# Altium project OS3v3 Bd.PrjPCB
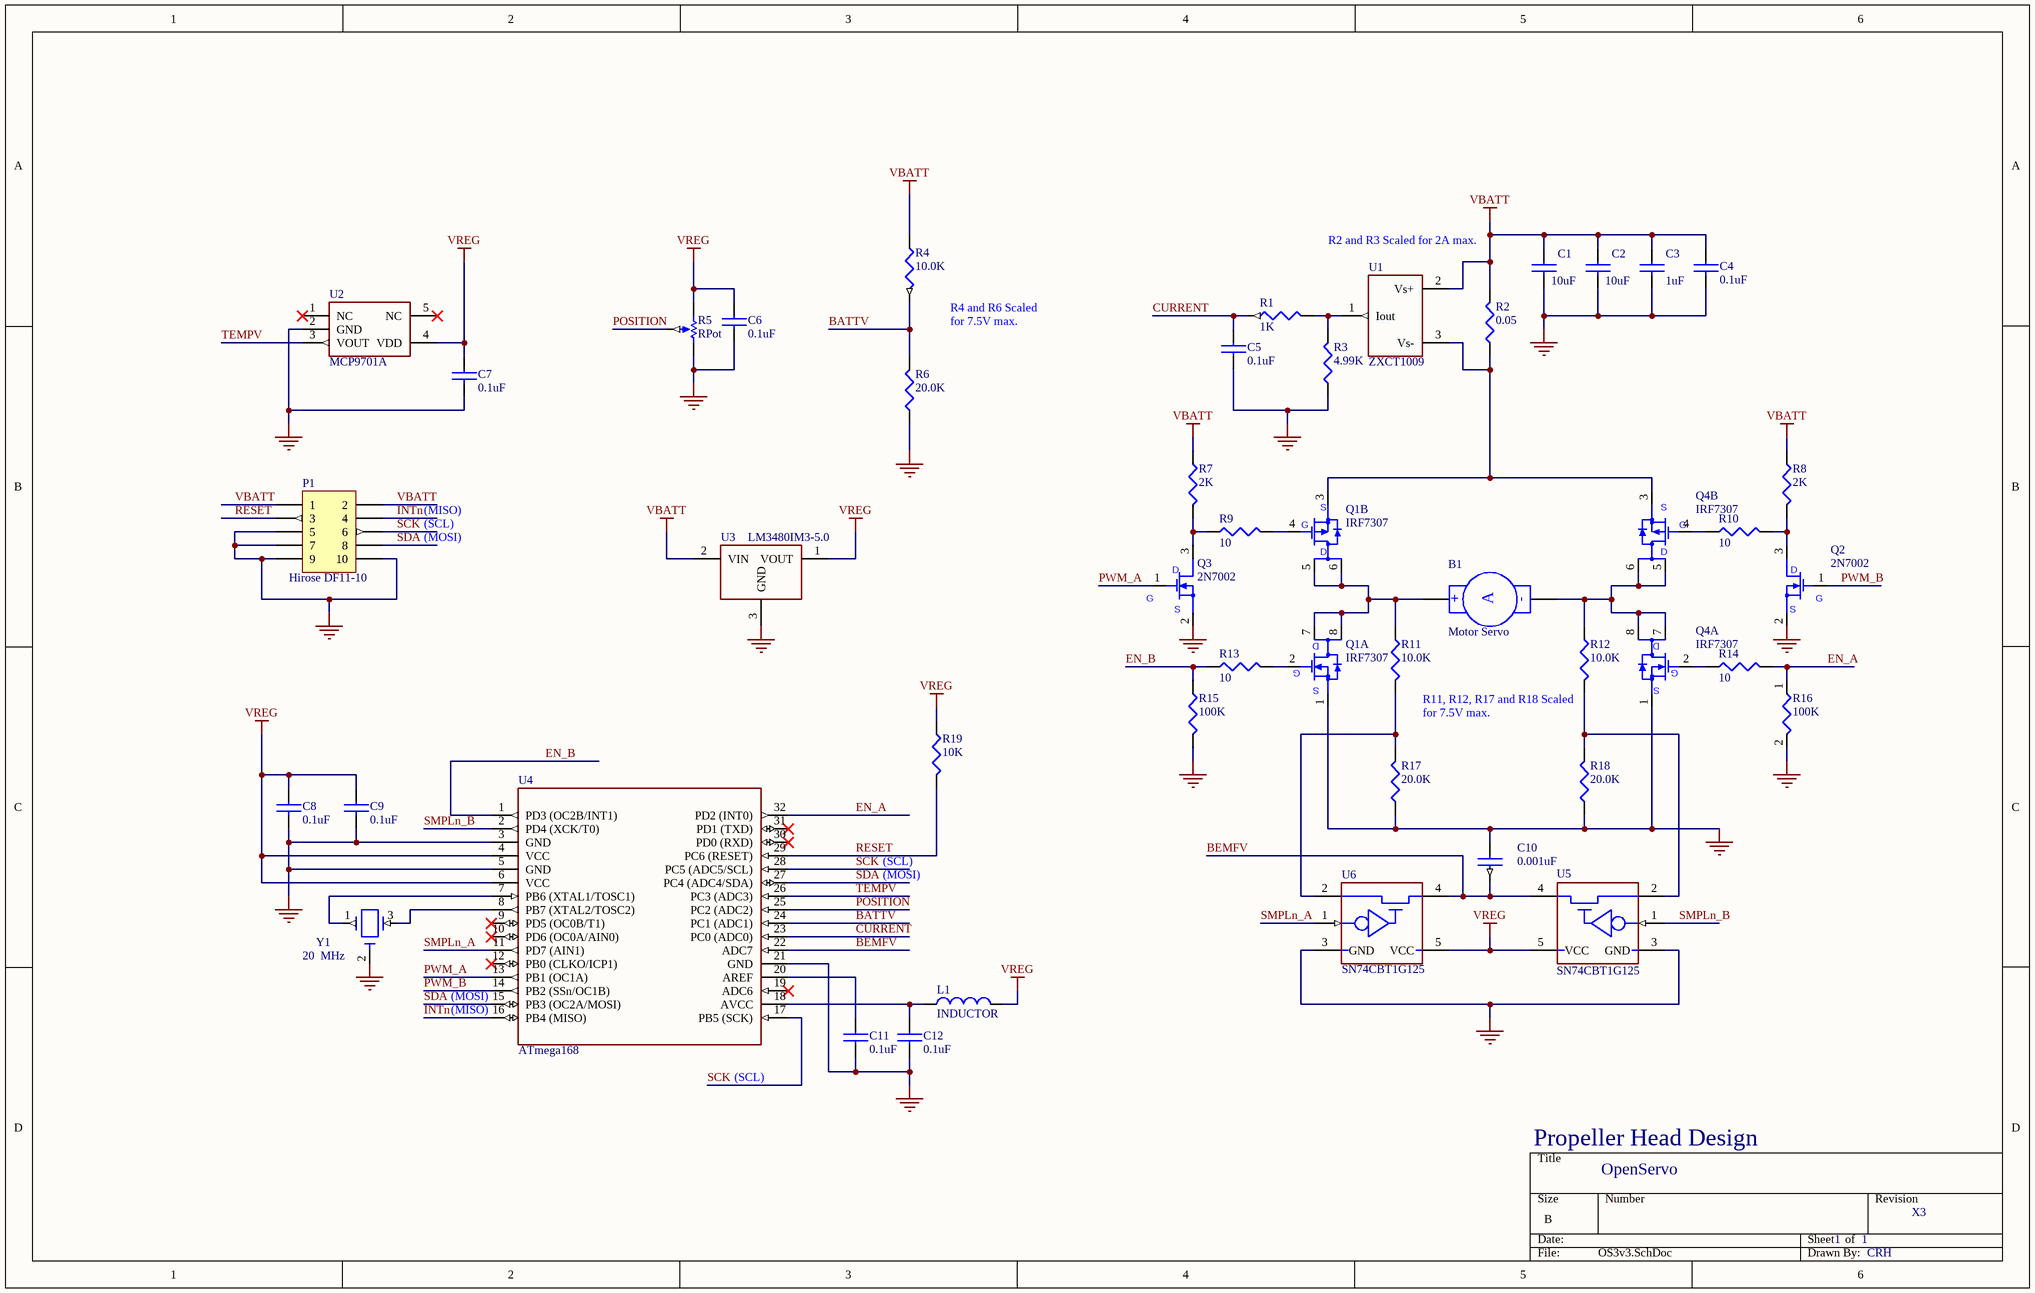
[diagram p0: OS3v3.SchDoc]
1 sheet, 45 parts. Net scope: global (net labels, ports and power ports of the same name join across sheets).
Board files: OSXv3_Pallet.PcbDoc, OS3v3.PcbDoc

## Sheet OS3v3.SchDoc: OpenServo
size B; CompanyName: Propeller Head Design; DrawnBy: CRH; Revision: X3; SheetNumber: 1; SheetTotal: 1

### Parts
B1  Motor Servo  [Servo Pads]  (no BOM)
C1  10uF  [C1206]
C2  10uF  [C1206]
C3  1uF  [C0603]
C4  0.1uF  [C0603]
C5  0.1uF  [C0603]
C6  0.1uF  [C0603]
C7  0.1uF  [C0603]
C8  0.1uF  [C0603]
C9  0.1uF  [C0603]
C10  0.001uF  [C0603]
C11  0.1uF  [C0603]
C12  0.1uF  [C0603]
L1  INDUCTOR  [C0603]
P1  Hirose DF11-10  [FD11-10E]
Q1  IRF7307  [SO8]  (parts A,B of 2)
Q2  2N7002  [SOT23-3]
Q3  2N7002  [SOT23-3]
Q4  IRF7307  [SO8]  (parts A,B of 2)
R1  1K  [R0603]
R2  0.05  [R0805]
R3  4.99K  [R0603]
R4  10.0K  [R0603]
R5  RPot  (no BOM)
R6  20.0K  [R0603]
R7  2K  [R0603]
R8  2K  [R0603]
R9  10  [R0603]
R10  10  [R0603]
R11  10.0K  [R0603]
R12  10.0K  [R0603]
R13  10  [R0603]
R14  10  [R0603]
R15  100K  [R0603]
R16  100K  [R0603]
R17  20.0K  [R0603]
R18  20.0K  [R0603]
R19  10K  [R0603]
U1  ZXCT1009  [SOT23-3F]
U2  MCP9701A  [SC70 -5]
U3  LM3480IM3-5.0  [SOT23-3]
U4  ATmega168  [32M1-A_N]
U5  SN74CBT1G125  [SC70 -5]
U6  SN74CBT1G125  [SC70 -5]
Y1  20  MHz  [MXC7T]

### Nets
GND: C1.2 C2.2 C3.2 C4.2 C5.2 C6.2 C7.2 C8.2 C9.2 C10.1 C11.2 C12.2 P1.5 P1.7 P1.9 P1.10 Q1.1(S) Q2.2(S) Q3.2(S) Q4.1(S) R3.2 R5.2(BOT) R6.2 R15.2 R16.2 R17.2 R18.2 U2.2(GND) U3.3(GND) U4.3(GND) U4.5(GND) U4.21(GND) U5.3(GND) U6.3(GND) Y1.2
VBATT: C1.1 C2.1 C3.1 C4.1 P1.1 P1.2 R2.1 R4.1 R7.1 R8.1 U1.2(Vs+) U3.2(VIN)
VREG: C6.1 C7.1 C8.1 C9.1 L1.2 R5.1(TOP) R19.1 U2.4(VDD) U3.1(VOUT) U4.4(VCC) U4.6(VCC) U5.5(VCC) U6.5(VCC)
BATTV: R4.2 R6.1 U4.24(PC1_(ADC1))
BEMFV: C10.2 U4.22(ADC7) U5.4(B) U6.4(B)
CURRENT: C5.1 R1.1 U4.23(PC0_(ADC0))
EN_A: R14.1 R16.1 U4.32(PD2_(INT0))
EN_B: R13.2 R15.1 U4.1(PD3_(OC2B/INT1))
INTn: P1.4 U4.16(PB4_(MISO))
POSITION: R5.3(TAP) U4.25(PC2_(ADC2))
PWM_A: Q3.1(G) U4.13(PB1_(OC1A))
PWM_B: Q2.1(G) U4.14(PB2_(SSn/OC1B))
RESET: P1.3 R19.2 U4.29(PC6_(RESET))
SCK: P1.6 U4.17(PB5_(SCK)) U4.28(PC5_(ADC5/SCL))
SDA: P1.8 U4.15(PB3_(OC2A/MOSI)) U4.27(PC4_(ADC4/SDA))
SMPLn_A: U4.11(PD7_(AIN1)) U6.1(OEn)
SMPLn_B: U4.2(PD4_(XCK/T0)) U5.1(OEn)
TEMPV: U2.3(VOUT) U4.26(PC3_(ADC3))
NetB1_1: B1.1(+) Q1.5(D) Q1.6(D) Q1.7(D) Q1.8(D) R11.1
NetB1_2: B1.2(-) Q4.5(D) Q4.6(D) Q4.7(D) Q4.8(D) R12.1
NetC11_1: C11.1 U4.20(AREF)
NetC12_1: C12.1 L1.1 U4.18(AVCC)
NetQ1_2: Q1.2(G) R13.1
NetQ1_3: Q1.3(S) Q4.3(S) R2.2 U1.3(Vs-)
NetQ1_4: Q1.4(G) R9.1
NetQ2_3: Q2.3(D) R8.2 R10.2
NetQ3_3: Q3.3(D) R7.2 R9.2
NetQ4_2: Q4.2(G) R14.2
NetQ4_4: Q4.4(G) R10.1
NetR1_2: R1.2 R3.1 U1.1(Iout)
NetR11_2: R11.2 R17.1 U6.2(A)
NetR12_2: R12.2 R18.1 U5.2(A)
NetU4_7: U4.7(PB6_(XTAL1/TOSC1)) Y1.1
NetU4_8: U4.8(PB7_(XTAL2/TOSC2)) Y1.3

Not connected (* = marked no-connect by the designer): U2 1(NC)* 5(NC)*; U4 9(PD5_(OC0B/T1))* 10(PD6_(OC0A/AIN0))* 12(PB0_(CLKO/ICP1))* 19(ADC6)* 30(PD0_(RXD))* 31(PD1_(TXD))*

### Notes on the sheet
- R2 and R3 Scaled for 2A max.
- R4 and R6 Scaled
- for 7.5V max.
- (MOSI)
- (SCL)
- (MISO)
- (near R12) R11, R12, R17 and R18 Scaled
- (near U4) (MOSI)
- (near U4) (MISO)

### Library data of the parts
B1 = Motor Servo: Servo Motor
C1 C2 = CAP NP: Manufacturer: Panasonic; Vendor: DigiKey; Vendor P/N: PCC2326CT-ND; Item Description: Capacitor, 10uF, X5R, ±20%, 25V, Ceramic, SM, 1206; Mfg. P/N: ECJ-3YB1E106M
C3 = CAP NP: Manufacturer: Panasonic; Vendor: DigiKey; Vendor P/N: PCC2224CT-ND; Item Description: Capacitor, 1uF, X5R, ±10%, 16V, Ceramic, SM, 0603; Mfg. P/N: ECJ-1VB1C105K
C4-C9 C11 C12 = CAP NP: Manufacturer: Panasonic; Vendor: DigiKey; Vendor P/N: PCC1762CT-ND; Item Description: Capacitor, 0.1uF, X7R, ±10%, 16V, Ceramic, SM, 0603; Mfg. P/N: ECJ-1VB1C104K
C10 = CAP NP: Manufacturer: Panasonic; Vendor: DigiKey; Vendor P/N: PCC1772CT-ND; Item Description: Capacitor, 0.001uF, X7R, ±10%, 50V, Ceramic, SM, 0603; Mfg. P/N: ECJ-1VB1H102K
L1 = INDUCTOR: Manufacturer: TDK; Item Description: Inductor, 10uH, 3mA, 10%; Mfg. P/N: MLF1608E100K; Vendor: DigiKey; Vendor P/N: 445-1025-1-ND
P1 = Header 5X2: Header, 5-Pin, Dual row; Item Description: Connector, TH, 2mm, 2x10; Mfg. P/N: DF11-10DP-2DSA(24); Vendor: DigiKey; Vendor P/N: H10232-ND
Q1 Q4 = IRF7307: Manufacturer: IRF; Item Description: MOSFET, Dual, N/P, 20/-20V, 4.3/-3.4A; Mfg. P/N: IRF7307TRPBF; Vendor: DigiKey; Vendor P/N: IRF7307PBFCT-ND
Q2 Q3 = 2N7002: N FET; Manufacturer: Diodes Inc.; Vendor: DigiKey; Vendor P/N: 2N7002-FDICT-ND; Item Description: FET, N, 60V, 115mA, Vgs 2.5V, SOT23
R1 = R: Manufacturer: Panasonic; Vendor: DigiKey; Vendor P/N: P1.0KGCT-ND; Item Description: Resistor, CF, 1K Ohms, 5%, 0.1W, SM, 0603; Mfg. P/N: ERJ-3GEYJ102V
R2 = R: 1%; Manufacturer: Susumu; Vendor: DigiKey; Vendor P/N: RL12T.05GCT-ND; Item Description: Resistor, CF, 0.05 Ohm, 0.25W,  2%, SM, 0805; Mfg. P/N: RL1220T-R050-G
R3 = R: 1%; Manufacturer: Panasonic; Vendor: DigiKey; Vendor P/N: P4.99KHCT-ND; Item Description: Resistor, CF, 4.99K Ohm, 0.06W, 1%, SM, 0603; Mfg. P/N: ERJ-3EKF4991V
R4 R11 R12 = R: 1%; Manufacturer: Panasonic; Vendor: DigiKey; Vendor P/N: P10.0KHCT-ND; Item Description: Resistor, CF, 10.0K Ohm, 1%, 0.06W, SM, 0603; Mfg. P/N: ERJ-3EKF1002V
R5 = RPot: Potentiometer; Item Description: Servo Pot
R6 R17 R18 = R: 1%; Manufacturer: Panasonic; Vendor: DigiKey; Vendor P/N: P20.0KHCT-ND; Item Description: Resistor, CF, 20.0K Ohm, 0.06W, 1%, SM, 0603; Mfg. P/N: ERJ-3EKF2002V
R7 R8 = R: Manufacturer: Panasonic; Vendor: DigiKey; Vendor P/N: P2.0KGCT-ND; Item Description: Resistor, CF, 2.0K Ohms, 5%, 0.1W, SM, 0603; Mfg. P/N: ERJ-3GEYJ202V
R9 R10 R13 R14 = R: Manufacturer: Panasonic; Vendor: DigiKey; Vendor P/N: P10GCT-ND; Item Description: Resistor, CF, 10 Ohms, 5%, 0.1W, SM, 0603; Mfg. P/N: ERJ-3GEYJ100V
R15 R16 = R: Manufacturer: Panasonic; Vendor: DigiKey; Vendor P/N: P100KGCT-ND; Item Description: Resistor, CF, 100K Ohms, 5%, 0.1W, SM, 0603; Mfg. P/N: ERJ-3GEYJ104V
R19 = R: Manufacturer: Panasonic; Vendor: DigiKey; Vendor P/N: P10KGCT-ND; Item Description: Resistor, CF, 10K Ohms, 5%, 0.1W, SM, 0603; Mfg. P/N: ERJ-3GEYJ103V
U1 = ZXCT1009: Manufacturer: ZETEX; Item Description: IC, HS Current Monitor, 20V, 10mA/V; Mfg. P/N: ZXCT1009FTA; Vendor: DigiKey; Vendor P/N: ZXCT1009FCT-ND
U2 = MCP9701A: Manufacturer: Microchip; Item Description: IC, Thermal Sensor, 19.5mV/C; Mfg. P/N: MCP9701AT-E/LT; Vendor: DigiKey; Vendor P/N: MCP9701AT-E/LTCT-ND
U3 = LM3480IM3-5.0: Manufacturer: National; Item Description: IC, Voltaage Regulator, 5V, 100mA. 1.2V DO; Mfg. P/N: LM3480IM3-5.0/NOPB; Vendor: DigiKey; Vendor P/N: LM3480IM3-5.0CT-ND
U4 = ATmega168: Manufacturer: Atmel; Item Description: IC, Microprocessor, ATmega168; Mfg. P/N: ATMEGA168-20MU; Vendor: DigiKey; Vendor P/N: ATMEGA168-20MU-ND
U5 U6 = SN74CBT1G125: Manufacturer: TI; Item Description: IC, FET Bus Switch, Single; Mfg. P/N: SN74CBT1G125DCKR; Vendor: DigiKey; Vendor P/N: 296-6410-1-ND
Y1 = CRYSTAL_0: Manufacturer: TDK; Item Description: Resionator, Ceramic, 20MHz., 0.5%; Mfg. P/N: CCR20.0MXC7T; Vendor: DigiKey; Vendor P/N: 445-1649-1-ND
